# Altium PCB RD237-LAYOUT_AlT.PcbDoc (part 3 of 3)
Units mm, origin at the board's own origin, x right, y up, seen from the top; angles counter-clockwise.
Board outline 100 x 82 mm, 4 copper layers (Top Layer, GND2, POWER 3, Bottom Layer), stack 1.444 mm thick; 308 components, 134 nets, 738 pads, 304 vias.
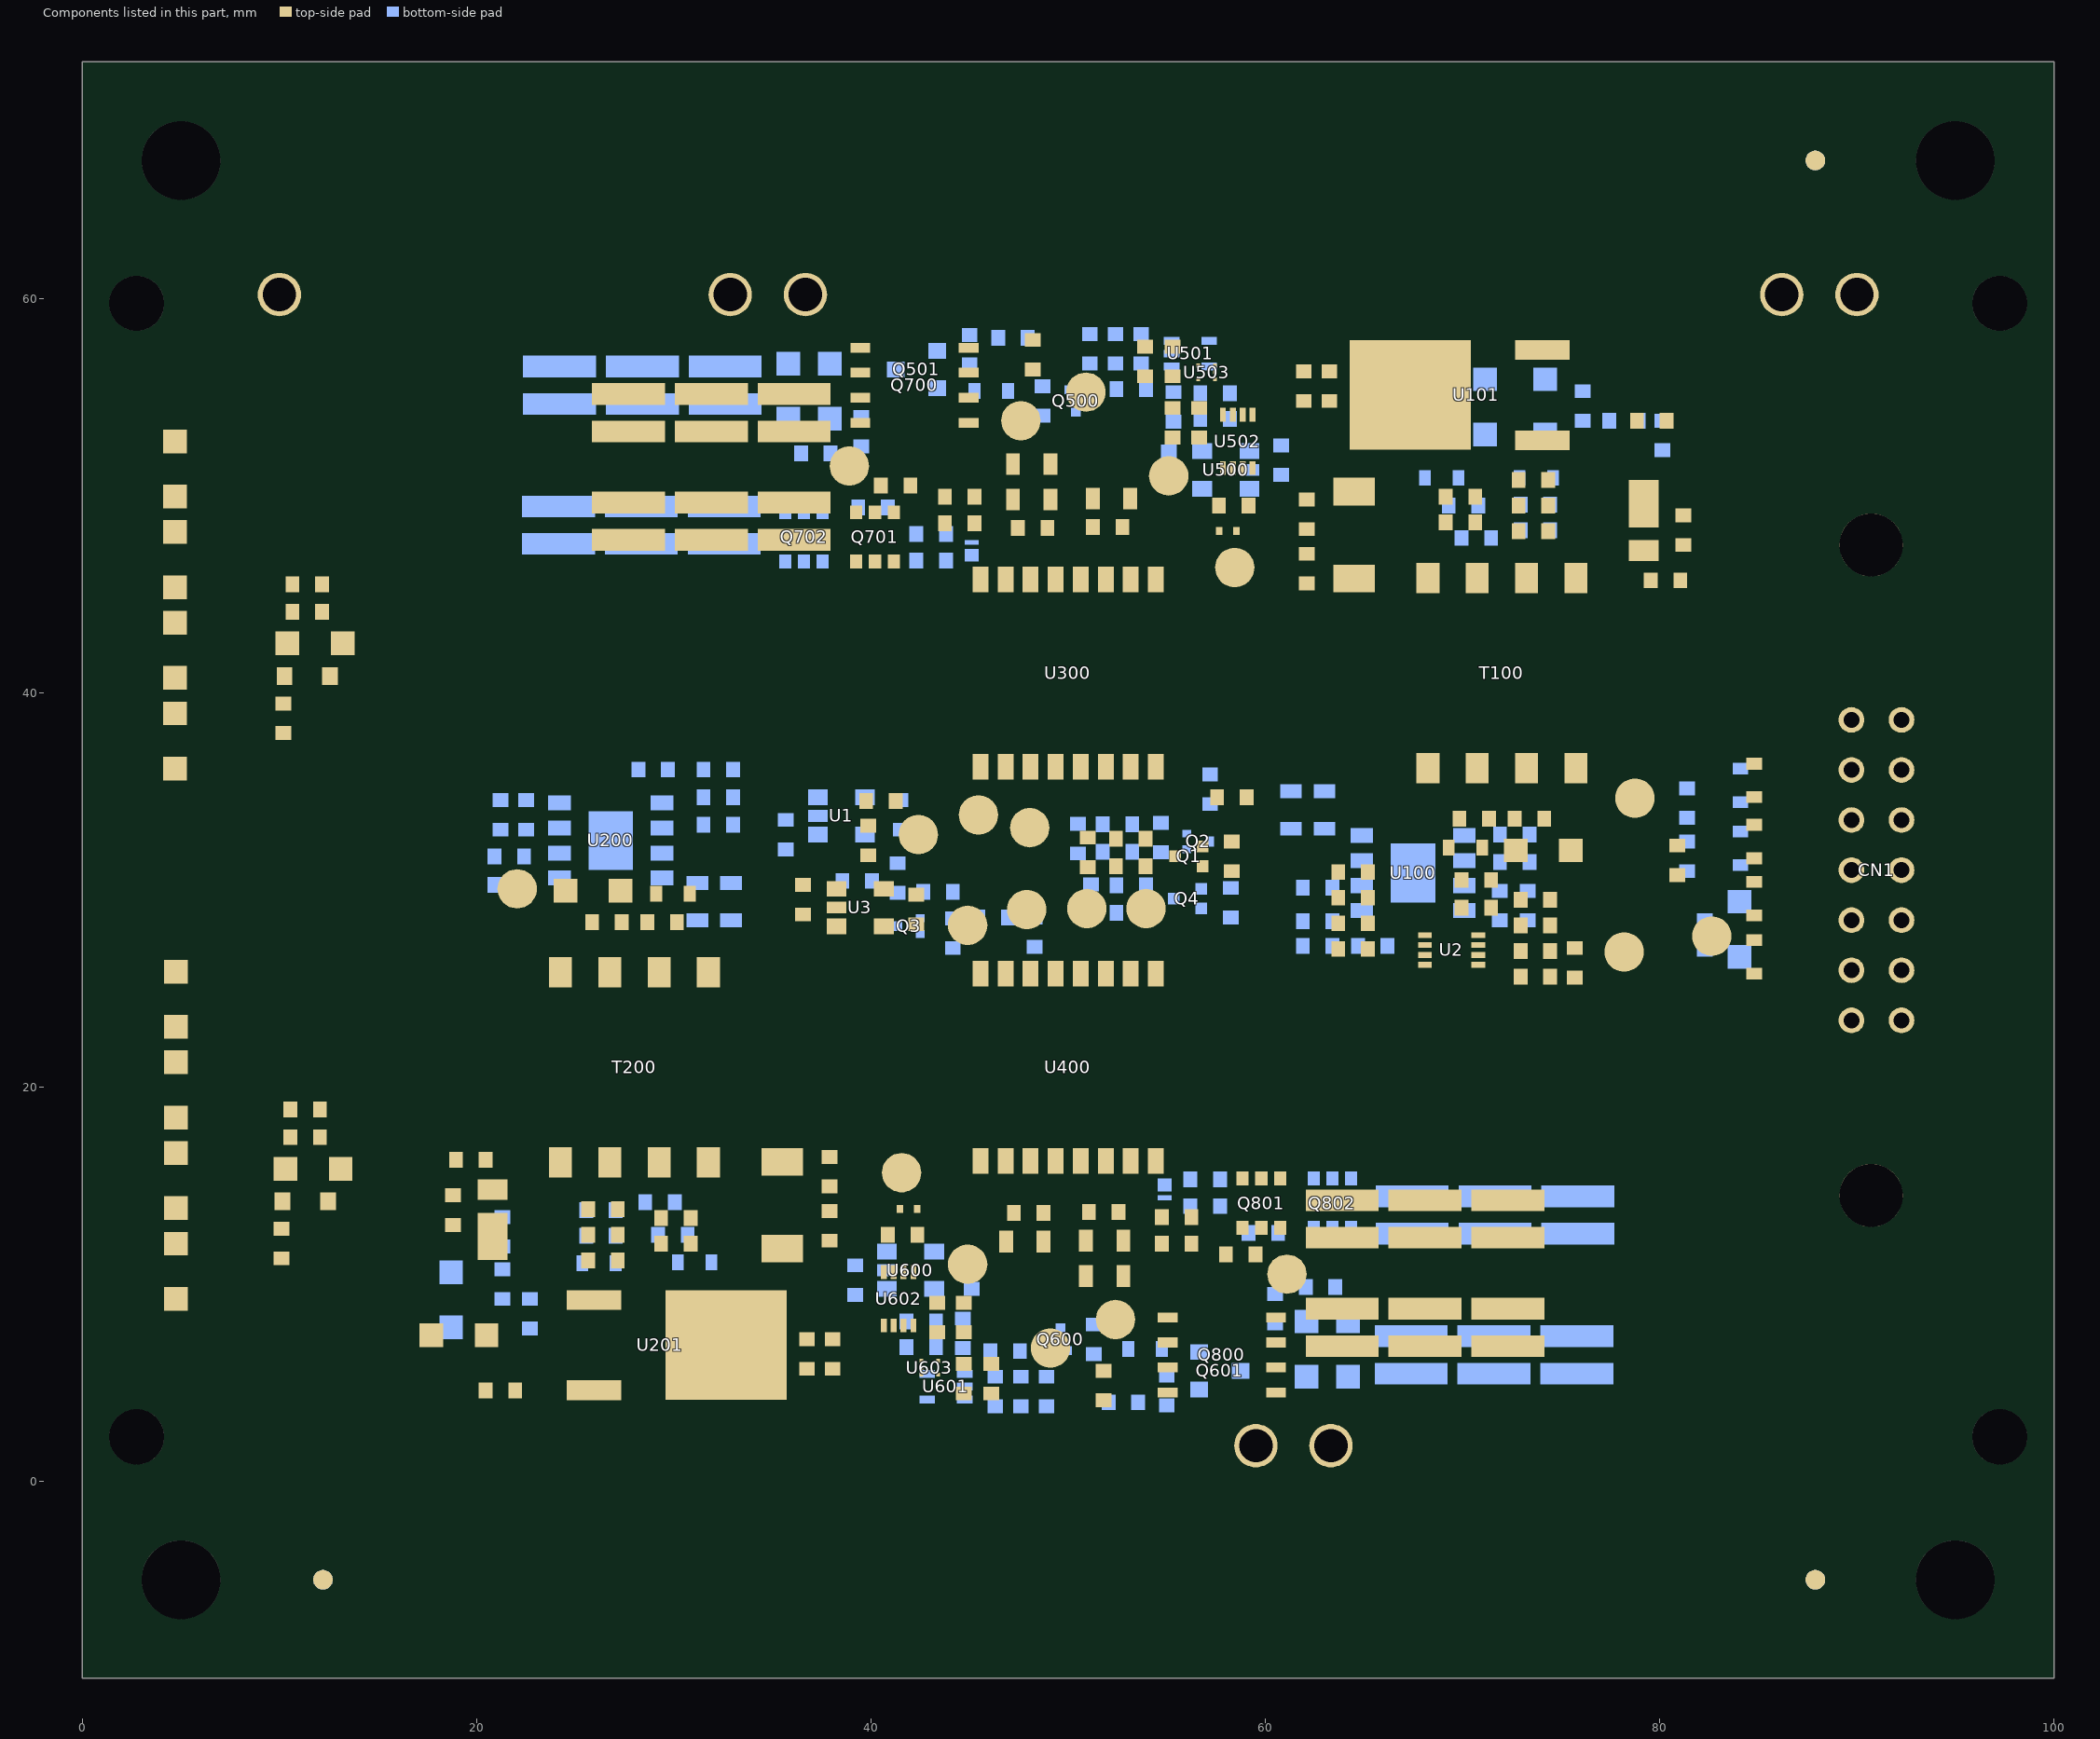
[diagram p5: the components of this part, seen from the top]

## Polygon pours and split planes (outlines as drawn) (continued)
GND on Top Layer "NONET_L04_P-001" (solid, remove dead copper, pour order 345): 17 vertices, not listed, extent 74.15,26.9 81.3,29.9
NetC104_1 on Top Layer "NONET_L04_P-001" (solid, remove dead copper, pour order 361): 24 vertices, not listed, extent 72.7,47.8 81.6,57.9
GND on Top Layer "11" (solid, remove dead copper, pour order 464): 18 vertices, not listed, extent 20,27.3 33.9,37
NetR700_2 on Top Layer "NONET_L04_P-001" (solid, remove dead copper, pour order 662): 18 vertices, not listed, extent 47.8,50.95 53.4,56.8
NetD707_1 on Top Layer "NONET_L04_P-001" (solid, remove dead copper, pour order 678): 37.9,49.35 37.9,49.25 37.75,49.1 26.1,49.1 25.85,49.35 25.85,53.5 26.15,53.8 37.85,53.8 37.9,53.75
no net on Top Layer "NONET_L04_P-001" (solid, remove dead copper, pour order 688): 51.5,4.45 51.4,4.35 51.4,3.35 51.5,3.25 55.35,3.25 55.5,3.4 55.5,4.65 55.4,4.75 52.5,4.75 52.2,4.45
NetR800_2 on Top Layer "NONET_L04_P-001" (solid, remove dead copper, pour order 719): 18 vertices, not listed, extent 46.6,5.2 52.2,11.05
NetD807_1 on Top Layer "NONET_L04_P-001" (solid, remove dead copper, pour order 723): 62.1,12.65 62.1,12.75 62.25,12.9 73.9,12.9 74.15,12.65 74.15,8.5 73.85,8.2 62.15,8.2 62.1,8.25
VEE_B on Top Layer "NONET_L04_P-001" (solid, remove dead copper, pour order 743): 77.8,17 77.15,16.35 77.15,3.8 77.65,3.3 95.1,3.3 96.35,4.55 96.35,12.9 95.9,13.35 87,13.35 83.35,17
VCC2_B on Bottom Layer "1" (solid, remove dead copper, pour order 425): 24 vertices, not listed, extent 14.3,3.3 38.6,9.7
VE_A on Bottom Layer "NONET_L04_P-001" (solid, remove dead copper, pour order 756): 83.2,53.8 83.3,53.7 83.3,51.9 83.2,51.8 79.85,51.8 79.75,51.9 79.75,52.65 80.75,52.65 80.85,52.75 80.85,53.7 80.95,53.8
NetC103_1 on Bottom Layer "2" (solid, remove dead copper, pour order 344): 74.25,33.7 74.35,33.6 74.35,31.7 74.65,31.4 78.05,31.4 78.25,31.6 78.25,35.5 77.2,36.55 69.8,36.55 69.5,36.25 69.5,32.65 69.7,32.45 72.2,32.45 72.2,33.55 72.35,33.7
VDD on Bottom Layer "NONET_L04_P-001" (solid, remove dead copper, pour order 346): 19 vertices, not listed, extent 59.9,30.6 65.45,33.4
GND on Bottom Layer "NONET_L04_P-001" (solid, remove dead copper, pour order 352): 26 vertices, not listed, extent 60.4,26.75 74.25,37
5V_B on Bottom Layer "NONET_L04_P-001" (solid, remove dead copper, pour order 175): 45.05,29.7 45.05,30.7 45.25,30.9 49.95,30.9 50.2,30.65 50.2,29.8 49.9,29.5 45.25,29.5
NetC203_1 on Bottom Layer "NONET_L04_P-001" (solid, remove dead copper, pour order 358): 22.2,30.65 22.05,30.5 22.05,27.15 22.25,26.95 24.75,26.95 25.05,27.25 25.05,30.5 24.9,30.65
GND on Bottom Layer "NONET_L04_P-001" (solid, remove dead copper, pour order 359): 29 vertices, not listed, extent 20.75,25 36.7,37.05
VE_A on Bottom Layer "NONET_L04_P-001" (solid, remove dead copper, pour order 368): 73.1,51.45 73.2,51.35 73.2,47.65 72.9,47.35 71.3,47.35 71.1,47.55 71.1,48.5 70.5,49.1 70.5,50.104 70.154,50.45 69.7,50.45 69.5,50.65 69.5,51.35 69.6,51.45
VEE_A on Bottom Layer "NONET_L04_P-001" (solid, remove dead copper, pour order 371): 68.35,51.35 65.8,51.35 65.6,51.15 65.6,48 66.15,47.45 69.5,47.45 70.1,47.45 70.3,47.65 70.3,48.2 69.6,48.9 69.6,49.8 69.55,49.85 68.7,49.85 68.4,50.15 68.4,51.3
VE_B on Bottom Layer "NONET_L04_P-001" (solid, remove dead copper, pour order 423): 26.9,10.55 26.8,10.65 26.8,14.35 27.1,14.65 28.7,14.65 28.9,14.45 28.9,13.5 29.5,12.9 29.5,11.896 29.846,11.55 30.3,11.55 30.5,11.35 30.5,10.65 30.4,10.55
NetC204_1 on Bottom Layer "NONET_L04_P-001" (solid, remove dead copper, pour order 424): 22.8,10.7 22.6,10.9 22.6,13.55 22.75,13.7 24.65,13.7 25.15,14.2 25.7,14.2 25.85,14.05 25.85,12.1 25.7,11.95 25.7,10.8 25.6,10.7
VEE_B on Bottom Layer "NONET_L04_P-001" (solid, remove dead copper, pour order 426): 17 vertices, not listed, extent 29.7,10.65 34.4,14.55
NetC104_1 on Bottom Layer "NONET_L04_P-001" (solid, remove dead copper, pour order 369): 17 vertices, not listed, extent 73.55,47.8 79,52.8
5V_A on Bottom Layer "NONET_L04_P-001" (solid, remove dead copper, pour order 176): 29 vertices, not listed, extent 39.2,31.7 56.3,37
GND on Bottom Layer "NONET_L04_P-001" (solid, remove dead copper, pour order 178): 20 vertices, not listed, extent 34.25,34.2 43.95,37
GND on Bottom Layer "NONET_L04_P-001" (solid, remove dead copper, pour order 190): 24 vertices, not listed, extent 34.25,33.2 39.25,37
VDD on Bottom Layer "NONET_L04_P-001" (solid, remove dead copper, pour order 357): 27 vertices, not listed, extent 28.85,29.6 37.8,33.2
VE_B on Bottom Layer "NONET_L04_P-001" (solid, remove dead copper, pour order 569): 40,9.9 39.911,9.811 36.761,9.811 36.6,9.65 36.6,8.1 37,7.7 39.5,7.7 41.2,9.4 41.2,9.8 41.1,9.9
VEE_B on Bottom Layer "NONET_L04_P-001" (solid, remove dead copper, pour order 570): 36.7,10.9 37,10.6 39.725,10.6 39.8,10.675 39.8,11.3 39.3,11.8 37,11.8 36.7,11.5
VE_A on Bottom Layer "NONET_L04_P-001" (solid, remove dead copper, pour order 612): 60,52.1 60.089,52.189 63.239,52.189 63.4,52.35 63.4,53.9 63,54.3 60.5,54.3 58.8,52.6 58.8,52.2 58.9,52.1
VEE_A on Bottom Layer "NONET_L04_P-001" (solid, remove dead copper, pour order 613): 63.3,51.1 63,51.4 60.275,51.4 60.2,51.325 60.2,50.7 60.7,50.2 63,50.2 63.3,50.5
NetC501_2 on Bottom Layer "NONET_L04_P-001" (solid, remove dead copper, pour order 614): 54.35,54.5 54,54.5 53.85,54.35 53.85,52.55 54.5,51.9 57.2,51.9 57.3,52 57.3,52.8 57.2,52.9 55.8,52.9 55.7,53 55.7,54 55.6,54.1 54.75,54.1
VEE_A on Bottom Layer "NONET_L04_P-001" (solid, remove dead copper, pour order 615): 55.7,48 55.9,48.2 55.9,50.6 55.4,51.1 54.5,51.1 54.05,50.65 54.05,48.2 54.25,48
VE_A on Bottom Layer "NONET_L04_P-001" (solid, remove dead copper, pour order 619): 37.65,51.8 37.75,51.7 39.95,51.7 40.25,51.4 41.75,51.4 41.95,51.6 41.95,52.9 41.8,53.05 40.45,53.05 40.2,52.8 37.85,52.8 37.65,52.6
GND on Bottom Layer "NONET_L04_P-001" (solid, remove dead copper, pour order 487): 30 vertices, not listed, extent 36.3,25 58.65,29.75
no net on Bottom Layer "NONET_L04_P642" (solid, pour order 642): 1,-1 1,-9 99,-9 99,-1
no net on Bottom Layer "NONET_L04_P649" (solid, pour order 649): 1,71 1,63 99,63 99,71
VEE_A on Bottom Layer "VEE_A_L04_P651" (solid, pour order 651): 85.5,54 85.7,53.8 85.7,47.4 83.9,45.6 83.1,45.6 82.9,45.8 82.9,50.8 84,51.9 84,53.7 84.3,54 84.9,54
VCC2_A on Bottom Layer "NONET_L04_P-001" (solid, remove dead copper, pour order 370): 77.925,54.475 77.95,54.5 78.4,54.5 78.4,57.3 77,58.7 61.65,58.7 61.4,58.45 61.4,56.05 62.1,55.35 74.828,55.35 75.204,55 76.7,55 77.2,54.5 77.9,54.5
NetD700_2 on Bottom Layer "NONET_L04_P-001" (solid, remove dead copper, pour order 658): 43.45,48.35 43.45,47.6 43.55,47.5 44.55,47.5 45.4,47.5 45.45,47.55 45.45,48.4 45.35,48.5 43.6,48.5
NetR713_2 on Bottom Layer "NONET_L04_P-001" (solid, remove dead copper, pour order 660): 46.05,49.05 46.75,48.35 46.75,46.95 47,46.7 48.3,46.7 48.5,46.9 48.5,48.6 47.05,50.05 40.65,50.05 40.5,49.9 40.5,49.1 40.55,49.05
NetQ701_3 on Bottom Layer "NONET_L04_P-001" (solid, remove dead copper, pour order 656): 41.7,48.4 41.5,48.2 41.5,45.1 41.6,45 43.6,45 43.75,45.15 43.75,45.6 43.55,45.8 43.05,45.8 42.7,46.15 42.7,48.3 42.6,48.4
VEE_A on Bottom Layer "NONET_L04_P-001" (solid, remove dead copper, pour order 641): 19 vertices, not listed, extent 42.9,54.9 50.15,57.4
NetR700_2 on Bottom Layer "NONET_L04_P-001" (solid, remove dead copper, pour order 665): 52.2,52.6 52.9,52.6 53.1,52.4 53.1,49.3 51.65,47.85 51.65,46.99 51.42,46.76 50.14,46.76 49.9,47 49.9,48.5 52,50.6 52,52.4
NetD501_1 on Bottom Layer "NONET_L04_P-001" (solid, remove dead copper, pour order 659): 57.2,45 57.35,45.15 57.35,47.1 56.89,47.56 52.16,47.56 52,47.4 52,46.6 51.57,46.17 46.03,46.17 45.5,46.7 45.5,47.05 45.45,47.1 43.45,47.1 43.45,46.2 44.65,45
NetR718_1 on Bottom Layer "NONET_L04_P-001" (solid, remove dead copper, pour order 669): 34.4,55.1 34.3,55.2 22.45,55.2 22.35,55.1 22.35,49.25 22.6,49 34.3,49 34.4,49.1
NetQ702_1 on Bottom Layer "NONET_L04_P-001" (solid, remove dead copper, pour order 671): 36.8,49.4 35.4,49.4 35.3,49.3 35.3,48.7 34.7,48.1 22.5,48.1 22.3,47.9 22.3,45.2 22.5,45 34.7,45 36,46.3 36.8,46.3 36.9,46.4 36.9,49.3
VEE_A on Bottom Layer "NONET_L04_P-001" (solid, remove dead copper, pour order 672): 37.5,47.3 39.6,47.3 39.9,47 39.9,45.2 39.7,45 36.2,45 36,45.2 36,45.6 36.2,45.8 37.2,45.8 37.4,46 37.4,47.2
NetQ702_3 on Bottom Layer "NONET_L04_P-001" (solid, remove dead copper, pour order 673): 37.625,50.025 37.45,49.85 37.45,48.8 37.75,48.5 39.45,48.5 39.75,48.8 39.75,49.85 39.575,50.025
VEE_A on Bottom Layer "NONET_L04_P-001" (solid, remove dead copper, pour order 674): 22 vertices, not listed, extent 35.2,50.5 44.3,54.45
NetD707_1 on Bottom Layer "NONET_L04_P-001" (solid, remove dead copper, pour order 675): 22.4,56.2 22.55,56.05 38.35,56.05 38.55,56.25 38.55,60.5 38.05,61 35.8,61 35.5,60.7 35.5,59.1 35,58.6 22.7,58.6 22.4,58.3
NetC601_2 on Bottom Layer "NONET_L04_P-001" (solid, remove dead copper, pour order 725): 45.65,7.5 46,7.5 46.15,7.65 46.15,9.45 45.5,10.1 42.8,10.1 42.7,10 42.7,9.2 42.8,9.1 44.2,9.1 44.3,9 44.3,8 44.4,7.9 45.25,7.9
VEE_B on Bottom Layer "NONET_L04_P-001" (solid, remove dead copper, pour order 726): 44.3,14 44.1,13.8 44.1,11.4 44.6,10.9 45.5,10.9 45.95,11.35 45.95,13.8 45.75,14
VE_B on Bottom Layer "NONET_L04_P-001" (solid, remove dead copper, pour order 727): 62.35,10.2 62.25,10.3 60.05,10.3 59.75,10.6 58.25,10.6 58.05,10.4 58.05,9.1 58.2,8.95 59.55,8.95 59.8,9.2 62.15,9.2 62.35,9.4
VEE_B on Bottom Layer "NONET_L04_P-001" (solid, remove dead copper, pour order 728): 19 vertices, not listed, extent 49.85,4.6 57.1,7.1
NetQ801_3 on Bottom Layer "NONET_L04_P-001" (solid, remove dead copper, pour order 729): 58.3,13.6 58.5,13.8 58.5,16.9 58.4,17 56.4,17 56.25,16.85 56.25,16.4 56.45,16.2 56.95,16.2 57.3,15.85 57.3,13.7 57.4,13.6
NetD800_2 on Bottom Layer "NONET_L04_P-001" (solid, remove dead copper, pour order 730): 56.55,13.65 56.55,14.4 56.45,14.5 55.45,14.5 54.6,14.5 54.55,14.45 54.55,13.6 54.65,13.5 56.4,13.5
NetD601_1 on Bottom Layer "NONET_L04_P-001" (solid, remove dead copper, pour order 731): 19 vertices, not listed, extent 42.65,14.44 56.55,17
NetR813_2 on Bottom Layer "NONET_L04_P-001" (solid, remove dead copper, pour order 732): 53.95,12.95 53.25,13.65 53.25,15.05 53,15.3 51.7,15.3 51.5,15.1 51.5,13.4 52.95,11.95 59.35,11.95 59.5,12.1 59.5,12.9 59.45,12.95
NetR800_2 on Bottom Layer "NONET_L04_P-001" (solid, remove dead copper, pour order 733): 47.8,9.4 47.1,9.4 46.9,9.6 46.9,12.7 48.35,14.15 48.35,15.01 48.58,15.24 49.86,15.24 50.1,15 50.1,13.5 48,11.4 48,9.6
NetR818_1 on Bottom Layer "NONET_L04_P-001" (solid, remove dead copper, pour order 734): 65.6,6.9 65.7,6.8 77.55,6.8 77.65,6.9 77.65,12.75 77.4,13 65.7,13 65.6,12.9
NetQ802_1 on Bottom Layer "NONET_L04_P-001" (solid, remove dead copper, pour order 735): 63.2,12.6 64.6,12.6 64.7,12.7 64.7,13.3 65.3,13.9 77.5,13.9 77.7,14.1 77.7,16.8 77.5,17 65.3,17 64,15.7 63.2,15.7 63.1,15.6 63.1,12.7
VEE_B on Bottom Layer "NONET_L04_P-001" (solid, remove dead copper, pour order 736): 62.5,14.7 60.4,14.7 60.1,15 60.1,16.8 60.3,17 63.8,17 64,16.8 64,16.4 63.8,16.2 62.8,16.2 62.6,16 62.6,14.8
NetQ802_3 on Bottom Layer "NONET_L04_P-001" (solid, remove dead copper, pour order 737): 62.375,11.975 62.55,12.15 62.55,13.2 62.25,13.5 60.55,13.5 60.25,13.2 60.25,12.15 60.425,11.975
VEE_B on Bottom Layer "NONET_L04_P-001" (solid, remove dead copper, pour order 738): 22 vertices, not listed, extent 55.7,7.55 64.8,11.5
NetD807_1 on Bottom Layer "NONET_L04_P-001" (solid, remove dead copper, pour order 739): 65,3.4 62.6,3.4 60.65,1.45 60.65,1.25 60.4,1 58.6,1 58.3,1.3 58.3,3.032 61.218,5.95 77.45,5.95 77.6,5.8 77.6,3.7 77.3,3.4
VEE_B on Bottom Layer "NONET_L04_P-001" (solid, remove dead copper, pour order 652): 37 vertices, not listed, extent 9.613,3.225 17.662,25.875
VEE_A on Bottom Layer "NONET_L04_P-001" (solid, remove dead copper, pour order 746): 19.45,58.75 16.3,55.6 13.9,55.6 9.55,51.25 9.55,35.85 10.15,35.25 11.9,35.25 12.1,35.45 12.1,37.15 20,45.05 21.15,45.05 21.8,45.7 21.8,58.65 21.7,58.75
VDD on Bottom Layer "NONET_L04_P-001" (solid, remove dead copper, pour order 348): 81.3,27.6 81.6,27.3 85.5,27.3 85.8,27.6 87.65,27.6 87.8,27.45 87.8,26.07 87.65,25.92 80.38,25.92 79.35,26.95 79.35,27.35 79.6,27.6
GND on Bottom Layer "NONET_L04_P-001" (solid, remove dead copper, pour order 351): 87.65,29.4 87.65,29.8 87.35,30.1 80.75,30.1 79.4,28.75 79.4,28.35 79.65,28.1 82.9,28.1 83.5,28.7 86.95,28.7
VEE_B on Bottom Layer "NONET_L04_P-001" (solid, remove dead copper, pour order 742): 78.7,17 78.5,16.8 78.5,3.5 78.7,3.3 95.1,3.3 96.35,4.55 96.35,12.9 95.9,13.35 87,13.35 83.35,17
VEE_B on POWER 3 "NONET_L04_P-001" (solid, remove dead copper, pour order 523): 18 vertices, not listed, extent 9.6,18.5 16.95,26.2
GND on POWER 3 "NONET_L04_P-001" (solid, remove dead copper, pour order 480): 20 vertices, not listed, extent 20,25 39.05,37
VDD on POWER 3 "NONET_L04_P-001" (solid, remove dead copper, pour order 360): 24 vertices, not listed, extent 34,21.35 96.344,32.5
no net on POWER 3 "NONET_L03_P645" (solid, pour order 645): 1,71 1,63 99,63 99,71
no net on POWER 3 "NONET_L03_P646" (solid, pour order 646): 1,-1 1,-9 99,-9 99,-1
VCC2_A on POWER 3 "2" (solid, remove dead copper, pour order 459): 50.397,57.997 50.397,56.885 48.4,54.888 48.4,51.2 48.9,50.7 51.25,50.7 51.5,50.95 51.5,52.4 52.05,52.95 60.15,52.95 64.2,57 64.2,58.5 63.9,58.8 51.2,58.8
NetD707_1 on POWER 3 "NONET_L04_P-001" (solid, remove dead copper, pour order 676): 26.9,50.55 26.65,50.8 26.65,53.15 26.9,53.4 35.05,53.4 35.55,53.9 35.55,60.7 35.85,61 37.75,61 38.1,60.65 38.1,52.3 36.35,50.55
VCC2_B on POWER 3 "2" (solid, remove dead copper, pour order 632): 49.603,4.003 49.603,5.115 51.6,7.112 51.6,10.7 51,11.3 48.75,11.3 48.5,11.05 48.5,9.6 47.95,9.05 39.85,9.05 36.05,5.25 36.05,3.65 36.5,3.2 48.8,3.2
NetD807_1 on POWER 3 "NONET_L04_P-001" (solid, remove dead copper, pour order 741): 61.9,7 57.95,3.05 57.95,1.45 58.4,1 60.4,1 60.7,1.3 60.7,1.55 67.75,8.6 73.1,8.6 73.35,8.85 73.35,11.2 73.1,11.45 66.35,11.45
VEE_A on POWER 3 "NONET_L04_P-001" (solid, remove dead copper, pour order 744): 19.4,58.75 15.5,54.85 15.5,54.35 15.9,53.95 23.05,53.95 23.8,54.7 23.8,58.4 23.45,58.75
VE_B on POWER 3 "NONET_L04_P-001" (solid, remove dead copper, pour order 462): 27 vertices, not listed, extent 9.2,3.3 61,19.65
VE_A on POWER 3 "1" (solid, remove dead copper, pour order 460): 39 vertices, not listed, extent 9.6,33.5 85.7,58.7
VEE_B on POWER 3 "NONET_L04_P-001" (solid, remove dead copper, pour order 505): 19 vertices, not listed, extent 60.15,3.247 96.35,17
GND on GND2 "NONET_L04_P-001" (solid, remove dead copper, pour order 490): 35.8,29.4 36.05,29.65 40.85,29.65 43.3,27.2 43.3,25.2 43.1,25 33.3,25 32.7,25.6 32.7,29.7 32.6,29.8 32.7,29.9 33.3,29.9 33.8,29.4
GND on GND2 "NONET_L04_P-001" (solid, remove dead copper, pour order 491): 29 vertices, not listed, extent 32.4,31.4 56.2,37
no net on GND2 "NONET_L02_P644" (solid, pour order 644): 1,71 1,63 99,63 99,71 1.4,71
VE_B on GND2 "NONET_L04_P-001" (solid, remove dead copper, pour order 747): 53.35,11.2 53.15,11 53.15,9.55 53.55,9.15 54.85,9.15 55.15,9.45 55.15,11 54.95,11.2
VE_A on GND2 "NONET_L04_P-001" (solid, remove dead copper, pour order 749): 46.65,50.8 46.85,51 46.85,52.45 46.45,52.85 45.15,52.85 44.85,52.55 44.85,51 45.05,50.8
VEE_A on GND2 "NONET_L04_P-001" (solid, remove dead copper, pour order 463): 49 vertices, not listed, extent 9.6,29.191 85.7,58.75
no net on GND2 "NONET_L02_P648" (solid, pour order 648): 1,-1 1,-9 99,-9 99,-1
GND on GND2 "NONET_L04_P-001" (solid, remove dead copper, pour order 451): 58 vertices, not listed, extent 20,21.4 95.2,40.85
VEE_B on GND2 "NONET_L04_P-001" (solid, remove dead copper, pour order 458): 55 vertices, not listed, extent 9.6,3.25 96.35,26.65

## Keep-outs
Keep-Out Layer:
  circle w0.1: c2.75,59.75 r6.4
  circle w0.1: c2.75,2.25 r6.4
  circle w0.1: c97.25,2.25 r6.4
  circle w0.1: c97.25,59.75 r6.4
  circle w0.1: c90.73,14.5 r2.6
  circle w0.1: c90.73,47.5 r2.6
  circle w0.1: c97.25,59.75 r2.4
  circle w0.1: c97.25,2.25 r2.4
  circle w0.1: c2.75,2.25 r2.4
  circle w0.1: c2.75,59.75 r2.4
  circle w0.1: c32.86,60.2 r1.85
  circle w0.1: c36.67,60.2 r1.85
  circle w0.1: c9.99,60.2 r1.85
  circle w0.1: c86.2,60.2 r1.85
  circle w0.1: c90.01,60.2 r1.85
  circle w0.1: c63.33,1.8 r1.85
  circle w0.1: c59.52,1.8 r1.85
  circle w0.1: c14.885,59.523 r4.4
  circle w0.1: c7.6,6.3 r4.4
  circle w0.1: c95,-5 r3
  circle w0.1: c5,-5 r3
  circle w0.1: c5,67 r3
  circle w0.1: c95,67 r3
  lines w0.1: 76.882,60.401 ccw(c82.869,60.001) 88.869,60.001
  lines w0.5: 3.6,58.9 3.6,36.6 3.6,3 96.6,3 96.6,59 ; 3.6,59 96.5,59
  lines w1: 0.5,61.5 0.5,0.5 99.5,0.5 99.5,61.5 0.55,61.5 ; 17.6,18.4 17.6,13.75 23.95,13.75 25.5,15.3 25.5,17.6 ; 30.5,17.9 30.5,15.3 31.6,14.2 35.7,14.2 36.95,12.95 38.9,12.95 38.9,16.9 ; 61.1,45.1 61.1,49.05 63.05,49.05 64.3,47.8 68.4,47.8 69.5,46.7 69.5,44.1 ; 74.5,44.4 74.5,46.7 76.05,48.25 82.4,48.25 82.4,44.6 ; 0.5,62.5 99.5,62.5 99.5,71.5 0.5,71.5 0.5,62.5 ; 0.5,62.5 0.5,62.5 ; 0.5,-9.5 99.5,-9.5 99.5,-0.5 0.5,-0.5 0.5,-9.5
  lines w2: 7.637,53.552 13.543,59.457 13.648,59.562 13.909,59.702 14.2,59.76 14.496,59.731 14.77,59.617 14.999,59.429 15.164,59.182 15.25,58.898 15.25,58.75 15.25,58.651 15.212,58.458 15.137,58.276 15.027,58.112 14.957,58.043 9.052,52.137 8.95,52.025 8.783,51.774 8.667,51.495 8.608,51.199 8.601,51.048 8.601,33.3 8.601,33.168 8.533,32.914 8.401,32.686 8.215,32.499 7.987,32.368 7.732,32.3 7.469,32.3 7.214,32.368 6.986,32.499 6.8,32.686 6.668,32.914 6.6,33.168 6.6,33.3 6.6,51.048 6.6,51.222 6.634,51.568 6.702,51.91 6.803,52.242 6.936,52.564 7.1,52.871 7.293,53.16 7.514,53.429 7.637,53.552 ; 7.637,53.552 7.637,53.552 ; 82,59 82,59.132 82.068,59.386 82.2,59.614 82.386,59.801 82.615,59.933 82.869,60.001 83.133,60.001 83.387,59.933 83.615,59.801 83.802,59.614 83.933,59.386 84.002,59.132 84.002,59 84.011,58.901 84.058,58.707 84.141,58.525 84.257,58.363 84.401,58.225 84.569,58.117 84.754,58.043 84.95,58.005 85.05,58 85.96,58 ; 82,59 82,59 ; 82,59 82.003,58.802 82.061,58.411 82.168,58.03 82.324,57.666 82.526,57.326 82.77,57.014 83.052,56.737 83.367,56.498 83.711,56.302 84.077,56.152 84.46,56.051 84.852,56 85.05,56 85.96,56 86.111,55.992 86.407,55.933 86.686,55.818 86.937,55.65 87.15,55.437 87.318,55.186 87.433,54.907 87.492,54.611 87.5,54.46 87.5,53.7 87.5,53.568 87.568,53.314 87.699,53.086 87.886,52.899 88.114,52.768 88.368,52.7 88.632,52.7 88.886,52.768 89.114,52.899 89.301,53.086 89.432,53.314 89.5,53.568 89.5,53.7 89.5,54.46 89.5,54.692 89.44,55.152 89.32,55.6 89.142,56.029 88.91,56.431 88.628,56.799 88.299,57.128 87.931,57.41 87.529,57.642 87.1,57.82 86.652,57.94 86.192,58 85.96,58 ; 85.96,58 85.96,58 ; 5,61.9 5,62 5,62.099 5.038,62.292 5.113,62.474 5.223,62.638 5.362,62.777 5.526,62.887 5.708,62.962 5.901,63 18.12,63 18.313,62.962 18.495,62.887 18.659,62.777 18.798,62.638 18.908,62.474 18.983,62.292 19.022,62.099 19.022,62 19.022,61.9 18.946,61.717 18.805,61.576 18.621,61.5 18.422,61.5 18.238,61.576 18.097,61.716 18.021,61.9 18.021,62 6,62 6,61.9 5.924,61.716 5.783,61.576 5.599,61.5 5.4,61.5 5.216,61.576 5.076,61.717 5,61.9 ; 6.6,7.168 6.6,7.3 6.6,25.36 6.6,25.592 6.66,26.052 6.78,26.5 6.958,26.929 7.19,27.331 7.472,27.699 7.801,28.028 8.169,28.31 8.571,28.542 9,28.72 9.448,28.84 9.908,28.9 15.499,28.9 15.692,28.862 15.874,28.787 16.038,28.677 16.177,28.538 16.287,28.374 16.362,28.192 16.4,27.999 16.4,27.9 16.4,27.801 16.362,27.608 16.287,27.426 16.177,27.262 16.038,27.123 15.874,27.013 15.692,26.938 15.499,26.9 10.14,26.9 9.989,26.892 9.693,26.833 9.414,26.718 9.163,26.55 8.95,26.337 8.782,26.086 8.667,25.807 8.608,25.511 8.6,25.36 8.6,7.3 8.6,7.168 8.532,6.914 8.401,6.686 8.214,6.499 7.986,6.368 7.732,6.3 7.468,6.3 7.214,6.368 6.986,6.499 6.799,6.686 6.668,6.914 6.6,7.168 ; 20,20.868 20,21.132 20.068,21.386 20.199,21.614 20.386,21.801 20.614,21.932 20.868,22 35.099,22 35.292,21.962 35.474,21.887 35.638,21.777 35.777,21.638 35.887,21.474 35.962,21.292 36,21.099 36,21 36,20.901 35.962,20.708 35.887,20.526 35.777,20.362 35.638,20.223 35.474,20.113 35.292,20.038 35.099,20 20.868,20 20.614,20.068 20.386,20.199 20.199,20.386 20.068,20.614 20,20.868 ; 26.9,61.901 26.9,62 26.9,62.098 26.938,62.291 27.013,62.472 27.122,62.636 27.261,62.775 27.424,62.884 27.606,62.959 27.799,62.997 41.792,62.997 41.965,62.963 42.128,62.895 42.275,62.797 42.4,62.672 42.498,62.525 42.566,62.362 42.6,62.188 42.6,62.1 42.6,62.007 42.534,61.834 42.41,61.696 42.244,61.612 42.06,61.593 41.881,61.641 41.731,61.75 41.63,61.906 41.61,61.996 27.9,61.996 27.9,61.897 27.822,61.714 27.681,61.574 27.497,61.499 27.299,61.5 27.116,61.576 26.975,61.717 26.9,61.901 ; 43,20.868 43,21.132 43.068,21.386 43.199,21.614 43.386,21.801 43.614,21.932 43.868,22 56.099,22 56.292,21.962 56.474,21.887 56.638,21.777 56.777,21.638 56.887,21.474 56.962,21.292 57,21.099 57,21 57,20.901 56.962,20.708 56.887,20.526 56.777,20.362 56.638,20.223 56.474,20.113 56.292,20.038 56.099,20 43.868,20 43.614,20.068 43.386,20.199 43.199,20.386 43.068,20.614 43,20.868 ; 43,40.868 43,41.132 43.068,41.386 43.199,41.614 43.386,41.801 43.614,41.932 43.868,42 56.099,42 56.292,41.962 56.474,41.887 56.638,41.777 56.777,41.638 56.887,41.474 56.962,41.292 57,41.099 57,41 57,40.901 56.962,40.708 56.887,40.526 56.777,40.362 56.638,40.223 56.474,40.113 56.292,40.038 56.099,40 43.868,40 43.614,40.068 43.386,40.199 43.199,40.386 43.068,40.614 43,40.868 ; 53.6,-0.099 53.6,0 53.6,0.1 53.676,0.283 53.816,0.424 54,0.5 54.199,0.5 54.383,0.424 54.524,0.284 54.6,0.1 54.6,0 68.3,0 68.3,0.1 68.376,0.284 68.517,0.424 68.701,0.5 68.9,0.5 69.084,0.424 69.224,0.283 69.3,0.1 69.3,0 69.3,-0.099 69.262,-0.292 69.187,-0.474 69.077,-0.638 68.938,-0.777 68.774,-0.887 68.592,-0.962 68.399,-1 54.501,-1 54.308,-0.962 54.126,-0.887 53.962,-0.777 53.823,-0.638 53.713,-0.474 53.638,-0.292 53.6,-0.099 ; 64,40.868 64,41.132 64.068,41.386 64.199,41.614 64.386,41.801 64.614,41.932 64.868,42 79.099,42 79.292,41.962 79.474,41.887 79.638,41.777 79.777,41.638 79.887,41.474 79.962,41.292 80,41.099 80,41 80,40.901 79.962,40.708 79.887,40.526 79.777,40.362 79.638,40.223 79.474,40.113 79.292,40.038 79.099,40 64.868,40 64.614,40.068 64.386,40.199 64.199,40.386 64.068,40.614 64,40.868 ; 76.712,61.9 76.712,62 76.712,62.099 76.75,62.292 76.825,62.474 76.935,62.638 77.074,62.777 77.238,62.887 77.42,62.962 77.613,63 94.299,63 94.492,62.962 94.674,62.887 94.838,62.777 94.977,62.638 95.087,62.474 95.162,62.292 95.2,62.099 95.2,62 95.2,61.9 95.124,61.717 94.984,61.576 94.8,61.5 94.601,61.5 94.417,61.576 94.276,61.716 94.2,61.9 94.2,62 77.712,62 77.712,61.9 77.636,61.716 77.495,61.576 77.311,61.5 77.112,61.5 76.928,61.576 76.788,61.717 76.712,61.9
  lines w8: 3,31.55 6.65,31.55 ; 7.6,3.1 7.6,7.3 ; 89.7,53.85 89.7,45.7 85,41 21,41 16,36 16,26 21,21 85,21 ; 98.75,17.35 88.65,17.35 85,21 ; 85,21 85,21

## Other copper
Top Layer:
  pour cut-out: 86.2,-5 ccw(c87.9,-5) 87.9,-6.7 ccw(c87.9,-5) 89.6,-5 ccw(c87.9,-5) 87.9,-3.3 ccw(c87.9,-5)
  pour cut-out: 86.2,67 ccw(c87.9,67) 87.9,65.3 ccw(c87.9,67) 89.6,67 ccw(c87.9,67) 87.9,68.7 ccw(c87.9,67)
  pour cut-out: 55,34.7 ccw(c55.6,34.7) 55.6,34.1 ccw(c55.6,34.7) 56.2,34.7 ccw(c55.6,34.7) 55.6,35.3 ccw(c55.6,34.7)
  pour cut-out: 10.5,-5 ccw(c12.2,-5) 12.2,-6.7 ccw(c12.2,-5) 13.9,-5 ccw(c12.2,-5) 12.2,-3.3 ccw(c12.2,-5)
  pour cut-out: 5,64 cw(c5,67) 2,67 cw(c5,67) 5,70 cw(c5,67) 8,67 cw(c5,67)
  pour cut-out: 92,67 ccw(c95,67) 95,64 ccw(c95,67) 98,67 ccw(c95,67) 95,70 ccw(c95,67)
  pour cut-out: 2,-5 ccw(c5,-5) 5,-8 ccw(c5,-5) 8,-5 ccw(c5,-5) 5,-2 ccw(c5,-5)
  pour cut-out: 92,-5 ccw(c95,-5) 95,-8 ccw(c95,-5) 98,-5 ccw(c95,-5) 95,-2 ccw(c95,-5)
POWER 3:
  pour cut-out: 37.45,26.05 ccw(c38.05,26.05) 38.05,25.45 ccw(c38.05,26.05) 38.65,26.05 ccw(c38.05,26.05) 38.05,26.65 ccw(c38.05,26.05)
  pour cut-out: 13.9,46.5 cw(c13.9,47.15) 13.9,47.8 46.65,47.8 cw(c46.65,47.15) 47.3,47.15 cw(c46.65,47.15) 46.65,46.5
  pour cut-out: 2,-5 ccw(c5,-5) 5,-8 ccw(c5,-5) 8,-5 ccw(c5,-5) 5,-2 ccw(c5,-5)
  pour cut-out: 92,-5 ccw(c95,-5) 95,-8 ccw(c95,-5) 98,-5 ccw(c95,-5) 95,-2 ccw(c95,-5)
  pour cut-out: 92,67 ccw(c95,67) 95,64 ccw(c95,67) 98,67 ccw(c95,67) 95,70 ccw(c95,67)
  pour cut-out: 5,64 cw(c5,67) 2,67 cw(c5,67) 5,70 cw(c5,67) 8,67 cw(c5,67)
  pour cut-out: 42,51.2 ccw(c42.9,51.2) 42.9,50.3 ccw(c42.9,51.2) 43.8,51.2 ccw(c42.9,51.2) 42.9,52.1 ccw(c42.9,51.2)
  pour cut-out: 43,51.2 ccw(c43.9,51.2) 43.9,50.3 ccw(c43.9,51.2) 44.8,51.2 ccw(c43.9,51.2) 43.9,52.1 ccw(c43.9,51.2)
  pour cut-out: 43,52.2 ccw(c43.9,52.2) 43.9,51.3 ccw(c43.9,52.2) 44.8,52.2 ccw(c43.9,52.2) 43.9,53.1 ccw(c43.9,52.2)
  pour cut-out: 42,52.2 ccw(c42.9,52.2) 42.9,51.3 ccw(c42.9,52.2) 43.8,52.2 ccw(c42.9,52.2) 42.9,53.1 ccw(c42.9,52.2)
  pour cut-out: 46.25,47.1 ccw(c47.15,47.1) 47.15,46.2 ccw(c47.15,47.1) 48.05,47.1 ccw(c47.15,47.1) 47.15,48 ccw(c47.15,47.1)
  pour cut-out: 45.2,47.1 ccw(c46.1,47.1) 46.1,46.2 ccw(c46.1,47.1) 47,47.1 ccw(c46.1,47.1) 46.1,48 ccw(c46.1,47.1)
  pour cut-out: 49.4,47.15 ccw(c50.3,47.15) 50.3,46.25 ccw(c50.3,47.15) 51.2,47.15 ccw(c50.3,47.15) 50.3,48.05 ccw(c50.3,47.15)
  pour cut-out: 50.35,47.15 ccw(c51.25,47.15) 51.25,46.25 ccw(c51.25,47.15) 52.15,47.15 ccw(c51.25,47.15) 51.25,48.05 ccw(c51.25,47.15)
  pour cut-out: 52.4,47.15 ccw(c53.3,47.15) 53.3,46.25 ccw(c53.3,47.15) 54.2,47.15 ccw(c53.3,47.15) 53.3,48.05 ccw(c53.3,47.15)
  pour cut-out: 51.45,47.15 ccw(c52.35,47.15) 52.35,46.25 ccw(c52.35,47.15) 53.25,47.15 ccw(c52.35,47.15) 52.35,48.05 ccw(c52.35,47.15)
  pour cut-out: 53,14.9 ccw(c53.9,14.9) 53.9,14 ccw(c53.9,14.9) 54.8,14.9 ccw(c53.9,14.9) 53.9,15.8 ccw(c53.9,14.9)
  pour cut-out: 51.95,14.9 ccw(c52.85,14.9) 52.85,14 ccw(c52.85,14.9) 53.75,14.9 ccw(c52.85,14.9) 52.85,15.8 ccw(c52.85,14.9)
  pour cut-out: 51,14.9 ccw(c51.9,14.9) 51.9,14 ccw(c51.9,14.9) 52.8,14.9 ccw(c51.9,14.9) 51.9,15.8 ccw(c51.9,14.9)
  pour cut-out: 48.8,14.85 ccw(c49.7,14.85) 49.7,13.95 ccw(c49.7,14.85) 50.6,14.85 ccw(c49.7,14.85) 49.7,15.75 ccw(c49.7,14.85)
  pour cut-out: 47.85,14.85 ccw(c48.75,14.85) 48.75,13.95 ccw(c48.75,14.85) 49.65,14.85 ccw(c48.75,14.85) 48.75,15.75 ccw(c48.75,14.85)
  pour cut-out: 46.75,14.85 ccw(c47.65,14.85) 47.65,13.95 ccw(c47.65,14.85) 48.55,14.85 ccw(c47.65,14.85) 47.65,15.75 ccw(c47.65,14.85)
  pour cut-out: 45.8,14.85 ccw(c46.7,14.85) 46.7,13.95 ccw(c46.7,14.85) 47.6,14.85 ccw(c46.7,14.85) 46.7,15.75 ccw(c46.7,14.85)
  pour cut-out: 47.2,47.1 ccw(c48.1,47.1) 48.1,46.2 ccw(c48.1,47.1) 49,47.1 ccw(c48.1,47.1) 48.1,48 ccw(c48.1,47.1)
GND2:
  pour cut-out: 5,64 cw(c5,67) 2,67 cw(c5,67) 5,70 cw(c5,67) 8,67 cw(c5,67)
  pour cut-out: 92,67 ccw(c95,67) 95,64 ccw(c95,67) 98,67 ccw(c95,67) 95,70 ccw(c95,67)
  pour cut-out: 92,-5 ccw(c95,-5) 95,-8 ccw(c95,-5) 98,-5 ccw(c95,-5) 95,-2 ccw(c95,-5)
  pour cut-out: 2,-5 ccw(c5,-5) 5,-8 ccw(c5,-5) 8,-5 ccw(c5,-5) 5,-2 ccw(c5,-5)
  pour cut-out: 47.2,47.1 ccw(c48.1,47.1) 48.1,46.2 ccw(c48.1,47.1) 49,47.1 ccw(c48.1,47.1) 48.1,48 ccw(c48.1,47.1)
  pour cut-out: 46.25,47.1 ccw(c47.15,47.1) 47.15,46.2 ccw(c47.15,47.1) 48.05,47.1 ccw(c47.15,47.1) 47.15,48 ccw(c47.15,47.1)
  pour cut-out: 45.2,47.1 ccw(c46.1,47.1) 46.1,46.2 ccw(c46.1,47.1) 47,47.1 ccw(c46.1,47.1) 46.1,48 ccw(c46.1,47.1)
  pour cut-out: 49.4,47.15 ccw(c50.3,47.15) 50.3,46.25 ccw(c50.3,47.15) 51.2,47.15 ccw(c50.3,47.15) 50.3,48.05 ccw(c50.3,47.15)
  pour cut-out: 50.35,47.15 ccw(c51.25,47.15) 51.25,46.25 ccw(c51.25,47.15) 52.15,47.15 ccw(c51.25,47.15) 51.25,48.05 ccw(c51.25,47.15)
  pour cut-out: 51.45,47.15 ccw(c52.35,47.15) 52.35,46.25 ccw(c52.35,47.15) 53.25,47.15 ccw(c52.35,47.15) 52.35,48.05 ccw(c52.35,47.15)
  pour cut-out: 52.4,47.15 ccw(c53.3,47.15) 53.3,46.25 ccw(c53.3,47.15) 54.2,47.15 ccw(c53.3,47.15) 53.3,48.05 ccw(c53.3,47.15)
  pour cut-out: 51.95,14.9 ccw(c52.85,14.9) 52.85,14 ccw(c52.85,14.9) 53.75,14.9 ccw(c52.85,14.9) 52.85,15.8 ccw(c52.85,14.9)
  pour cut-out: 51,14.9 ccw(c51.9,14.9) 51.9,14 ccw(c51.9,14.9) 52.8,14.9 ccw(c51.9,14.9) 51.9,15.8 ccw(c51.9,14.9)
  pour cut-out: 53,14.9 ccw(c53.9,14.9) 53.9,14 ccw(c53.9,14.9) 54.8,14.9 ccw(c53.9,14.9) 53.9,15.8 ccw(c53.9,14.9)
  pour cut-out: 48.8,14.85 ccw(c49.7,14.85) 49.7,13.95 ccw(c49.7,14.85) 50.6,14.85 ccw(c49.7,14.85) 49.7,15.75 ccw(c49.7,14.85)
  pour cut-out: 46.75,14.85 ccw(c47.65,14.85) 47.65,13.95 ccw(c47.65,14.85) 48.55,14.85 ccw(c47.65,14.85) 47.65,15.75 ccw(c47.65,14.85)
  pour cut-out: 45.8,14.85 ccw(c46.7,14.85) 46.7,13.95 ccw(c46.7,14.85) 47.6,14.85 ccw(c46.7,14.85) 46.7,15.75 ccw(c46.7,14.85)
  pour cut-out: 47.85,14.85 ccw(c48.75,14.85) 48.75,13.95 ccw(c48.75,14.85) 49.65,14.85 ccw(c48.75,14.85) 48.75,15.75 ccw(c48.75,14.85)
  pour cut-out: 42.45,45.4 ccw(c43.35,45.4) 43.35,44.5 ccw(c43.35,45.4) 44.25,45.4 ccw(c43.35,45.4) 43.35,46.3 ccw(c43.35,45.4)
  pour cut-out: 41.5,45.4 ccw(c42.4,45.4) 42.4,44.5 ccw(c42.4,45.4) 43.3,45.4 ccw(c42.4,45.4) 42.4,46.3 ccw(c42.4,45.4)
Bottom Layer:
  pour cut-out: 86.2,67 ccw(c87.9,67) 87.9,65.3 ccw(c87.9,67) 89.6,67 ccw(c87.9,67) 87.9,68.7 ccw(c87.9,67)
  pour cut-out: 43.6,26 ccw(c44.2,26) 44.2,25.4 ccw(c44.2,26) 44.8,26 ccw(c44.2,26) 44.2,26.6 ccw(c44.2,26)
  pour cut-out: 68,28.75 ccw(c68.6,28.75) 68.6,28.15 ccw(c68.6,28.75) 69.2,28.75 ccw(c68.6,28.75) 68.6,29.35 ccw(c68.6,28.75)
  pour cut-out: 86.2,-5 ccw(c87.9,-5) 87.9,-6.7 ccw(c87.9,-5) 89.6,-5 ccw(c87.9,-5) 87.9,-3.3 ccw(c87.9,-5)
  pour cut-out: 10.5,-5 ccw(c12.2,-5) 12.2,-6.7 ccw(c12.2,-5) 13.9,-5 ccw(c12.2,-5) 12.2,-3.3 ccw(c12.2,-5)
  pour cut-out: 2,-5 ccw(c5,-5) 5,-8 ccw(c5,-5) 8,-5 ccw(c5,-5) 5,-2 ccw(c5,-5)
  pour cut-out: 92,-5 ccw(c95,-5) 95,-8 ccw(c95,-5) 98,-5 ccw(c95,-5) 95,-2 ccw(c95,-5)
  pour cut-out: 92,67 ccw(c95,67) 95,64 ccw(c95,67) 98,67 ccw(c95,67) 95,70 ccw(c95,67)
  pour cut-out: 5,64 cw(c5,67) 2,67 cw(c5,67) 5,70 cw(c5,67) 8,67 cw(c5,67)

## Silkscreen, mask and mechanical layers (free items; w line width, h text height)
Top Overlay:
  drawing of 636 lines, arcs and shapes, not listed
  text "1947" at 52.25,44.05 h0.7
  text "TLP5231" at 49.55,42.95 h0.8
  text "J7" at 53.25,37.9 h0.8
  text "SiC MOSFET Module  / Gate Driver" at 13.094,37 h1
  text "1947" at 52.25,24.05 h0.7
  text "TLP5231" at 49.55,22.95 h0.8
  text "A" at 17.5,19.7 h0.7
  text "J7" at 53.25,17.9 h0.8
  text "A" at 23.95,13.75 h0.7
Bottom Overlay:
  drawing of 236 lines, arcs and shapes, not listed
Top Solder:
  drawing of 444 lines, arcs and shapes, not listed
Bottom Solder:
  drawing of 444 lines, arcs and shapes, not listed
Mechanical 4:
  drawing of 451 lines, arcs and shapes, not listed
  text "V-CUT" at 104.5,60.9 h0.7
  text "V-CUT" at 104.5,-1.1 h0.7
Mechanical 6:
  drawing of 436 lines, arcs and shapes, not listed
Mechanical 11:
  lines w0.2: 0,0 100,0
Drill Drawing:
  circle w0.254: c-51.544,102.49 r0.847
  lines w0.254: -52.391,82.594 -52.391,83.017 -51.967,83.44 -52.391,83.863 -52.391,84.287 -51.967,84.287 -51.544,83.863 -51.121,84.287 -50.697,84.287 -50.697,83.863 -51.121,83.44 -50.697,83.017 -50.697,82.594 -51.121,82.594 -51.544,83.017 -51.967,82.594 -52.391,82.594 ; -52.391,86.404 -50.697,86.404 -50.697,88.097 -52.391,88.097 -52.391,86.404 ; -52.391,90.637 -51.967,90.637 -51.544,90.214 -51.121,90.637 -50.697,90.637 -51.121,91.06 -50.697,91.483 -51.121,91.483 -51.544,91.907 -51.967,91.483 -52.391,91.483 -51.967,91.06 -52.391,90.637 ; -52.391,94.447 -51.967,94.447 -51.967,94.024 -51.121,94.024 -51.121,94.447 -50.697,94.447 -50.697,95.293 -51.121,95.293 -51.121,95.717 -51.967,95.717 -51.967,95.293 -52.391,95.293 -52.391,94.447 ; -52.391,99.527 -50.697,99.527 -51.544,97.834 -52.391,99.527
  lines w0.381: -53.91,81.451 229.577,81.451 ; -53.91,104.311 229.577,104.311 ; -39.917,77.641 -39.917,108.121 ; -24.681,77.641 -24.681,108.121 ; 4.52,77.641 4.52,108.121 ; 17.369,77.641 17.369,108.121 ; 36.008,77.641 36.008,108.121 ; 74.097,77.641 74.097,108.121 ; 89.079,77.641 89.079,108.121 ; 108.022,77.641 108.022,108.121 ; 139.001,77.641 139.001,108.121 ; 160.686,77.641 160.686,108.121 ; 194.56,77.641 194.56,108.121 ; -53.91,77.641 229.577,77.641 229.577,108.121 -53.91,108.121 -53.91,77.641
  text "Symbol" at -51.624,105.454 h1.83
  text "Count" at -38.774,105.454 h1.83
  text "Hole Size" at -23.538,105.454 h1.83
  text "Plated" at 5.663,105.454 h1.83
  text "Hole Type" at 18.512,105.454 h1.83
  text "Drill Layer Pair" at 37.151,105.454 h1.83
  text "Via/Pad" at 75.24,105.454 h1.83
  text "Pad Shape" at 90.222,105.454 h1.83
  text "Template" at 109.165,105.454 h1.83
  text "Description" at 140.144,105.454 h1.83
  text "Hole Tolerance (+)" at 161.829,105.454 h1.83
  text "Hole Tolerance (-)" at 195.703,105.454 h1.83
  text "2" at -38.774,101.644 h1.52
  text "3.200mm (125.98mil)" at -23.538,101.644 h1.52
  text "NPTH" at 5.663,101.644 h1.52
  text "Round" at 18.512,101.644 h1.52
  text "Top Layer - Bottom Layer" at 37.151,101.644 h1.52
  text "Pad" at 75.24,101.644 h1.52
  text "Rounded" at 90.222,101.644 h1.52
  text "c320hn320m325" at 109.165,101.644 h1.52
  text "4" at -38.774,97.834 h1.52
  text "2.800mm (110.24mil)" at -23.538,97.834 h1.52
  text "NPTH" at 5.663,97.834 h1.52
  text "Round" at 18.512,97.834 h1.52
  text "Top Layer - Bottom Layer" at 37.151,97.834 h1.52
  text "Pad" at 75.24,97.834 h1.52
  text "Rounded" at 90.222,97.834 h1.52
  text "c280hn280m330" at 109.165,97.834 h1.52
  text "4" at -38.774,94.024 h1.52
  text "4.000mm (157.48mil)" at -23.538,94.024 h1.52
  text "NPTH" at 5.663,94.024 h1.52
  text "Round" at 18.512,94.024 h1.52
  text "Top Layer - Bottom Layer" at 37.151,94.024 h1.52
  text "Pad" at 75.24,94.024 h1.52
  text "Rounded" at 90.222,94.024 h1.52
  text "c400hn400m450" at 109.165,94.024 h1.52
  text "7" at -38.774,90.214 h1.52
  text "1.700mm (66.93mil)" at -23.538,90.214 h1.52
  text "PTH" at 5.663,90.214 h1.52
  text "Round" at 18.512,90.214 h1.52
  text "Top Layer - Bottom Layer" at 37.151,90.214 h1.52
  text "Pad" at 75.24,90.214 h1.52
  text "Rounded" at 90.222,90.214 h1.52
  text "c220h170m225" at 109.165,90.214 h1.52
  text "14" at -38.774,86.404 h1.52
  text "0.800mm (31.50mil)" at -23.538,86.404 h1.52
  text "PTH" at 5.663,86.404 h1.52
  text "Round" at 18.512,86.404 h1.52
  text "Top Layer - Bottom Layer" at 37.151,86.404 h1.52
  text "Pad" at 75.24,86.404 h1.52
  text "Rounded" at 90.222,86.404 h1.52
  text "c130h80m135(Tol10-0)" at 109.165,86.404 h1.52
  text "0.100mm (3.94mil)" at 161.829,86.404 h1.52
  text "0.000mm (0.00mil)" at 195.703,86.404 h1.52
  text "304" at -38.774,82.594 h1.52
  text "0.400mm (15.75mil)" at -23.538,82.594 h1.52
  text "PTH" at 5.663,82.594 h1.52
  text "Round" at 18.512,82.594 h1.52
  text "Top Layer - Bottom Layer" at 37.151,82.594 h1.52
  text "Via" at 75.24,82.594 h1.52
  text "Rounded" at 90.222,82.594 h1.52
  text "v80h40m70" at 109.165,82.594 h1.52
  text "335 Total" at -38.774,78.784 h1.52

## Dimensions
0,-10 to 0,0 on Mechanical 5
0,0 to 0,62 on Mechanical 5
0,72 to 0,62 on Mechanical 5
97.25,59.75 to 97.25,2.25 on Mechanical 5
2.75,59.75 to 9.99,60.2 on Mechanical 5
32.86,60.2 to 2.75,59.75 on Mechanical 5
36.67,60.2 to 2.75,60.104 on Mechanical 5
59.52,1.8 to 2.75,60.104 on Mechanical 5
63.33,1.8 to 2.75,59.75 on Mechanical 5
86.2,60.2 to 2.75,59.75 on Mechanical 5
90.01,60.2 to 2.75,59.75 on Mechanical 5
97.25,59.75 to 2.75,59.75 on Mechanical 5
0,62 to 100,62 on Mechanical 5
9.99,60.2 to 59.52,1.8 on Mechanical 5
64.6,1.75 to 70.55,1.75 on Mechanical 5
98.35,0.6 to 101.05,-1.8 on Mechanical 5
97.05,-6.8 to 100.65,-10.4 on Mechanical 5
89.05,15.5 to 86.5,18.1 on Mechanical 5
5,67 to 0,72 on Mechanical 5
5,-5 to 0,-10 on Mechanical 5
0,72 to 5,67 on Mechanical 5
95,-5 to 100,-10 on Mechanical 5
